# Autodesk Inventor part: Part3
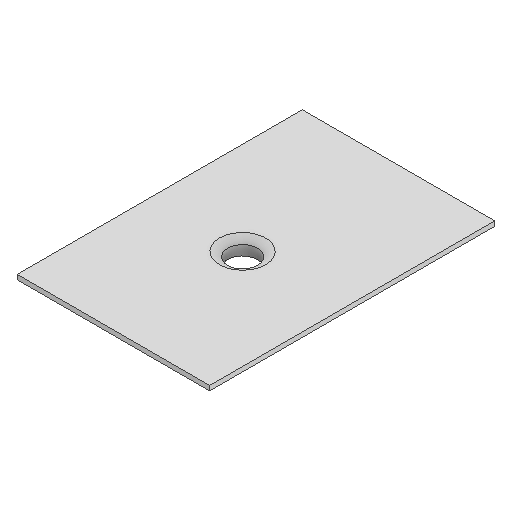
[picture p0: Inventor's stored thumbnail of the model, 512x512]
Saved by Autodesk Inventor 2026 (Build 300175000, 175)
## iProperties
Created: 2025-03
Part Number: Part3
Material: Generic
Document SubType Name: Sheet Metal
Designer: zhangy5
Density: 1 g/cm^3
Sheet Metal Rule: Default
Appearance: Default
Author: zhangy5
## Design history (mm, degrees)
node "Face1"
  sketch "Sketch1"
    geometry: L1 (59.917, 85.629)-(-64.398, 85.629); L2 (-64.398, 85.629)-(-64.398, -98.534); L3 (-64.398, -98.534)-(59.917, -98.534); L4 (59.917, -98.534)-(59.917, 85.629); 1 further point
    constraints: 8 end point, 2 parallel, 1 horizontal, 1 perpendicular
workplane "Work Plane1"
sketch "Sketch3"
  geometry: C1 r 12.7 at (0, 0); 1 further point
  constraints: 1 centre point, 1 coincident
  dimensions: "Diameter" = 25.4 diameter of C1
extrude "Extrusion2" join sketch "Sketch3" taper "d6" = 0 deg; distance "Height" = 6.35
sketch "Sketch4"
  geometry: C1 r 9.652 at (0, 0)
  constraints: 1 centre point
  dimensions: "d7" = 19.304 diameter of C1 (= Diameter - 2 x Thickness)
extrude "Extrusion3" cut sketch "Sketch4" distance "d8" = 9.398 (= Height + Thickness); taper "d9" = 0 deg
sketch "Sketch5"
  geometry: C1 r 9.652 at (0, 0); 1 further point
  constraints: 1 centre point, 1 coincident
  dimensions: "d17" = 19.304 diameter of C1 (= d7)
extrude "Extrusion4" cut sketch "Sketch5" distance "d15" = 3.048 (= Thickness); taper "Angle" = 60 deg
chamfer "Chamfer3" distance "d21" = 1.524 (= 0.5 x Thickness); stored, may be unused: second distance "d22" = 3.175, angle "d23" = 30 deg (computed from Angle)
body "Solid1"
face "Plate1" dims "d0" = 3.048 (= Thickness)
other parameters: "Thickness" = 3.048, "BendRadius" = 3.048 (= Thickness), "BendReliefWidth" = 3.048 (= Thickness), "BendReliefDepth" = 1.524 (= 0.5 x Thickness), "CornerReliefSize" = 12.192 (= 4 x Thickness), "SeamGap" = 0.00508, "MinimumRemnant" = 6.096 (= 2 x Thickness), "TransitionRadius" = 3.048 (= BendRadius), "JacobiRadiusSize" = 3.048 (= BendRadius), "GapSize" = 3.048 (= Thickness), "d13" = -3.048 (= -Thickness)
